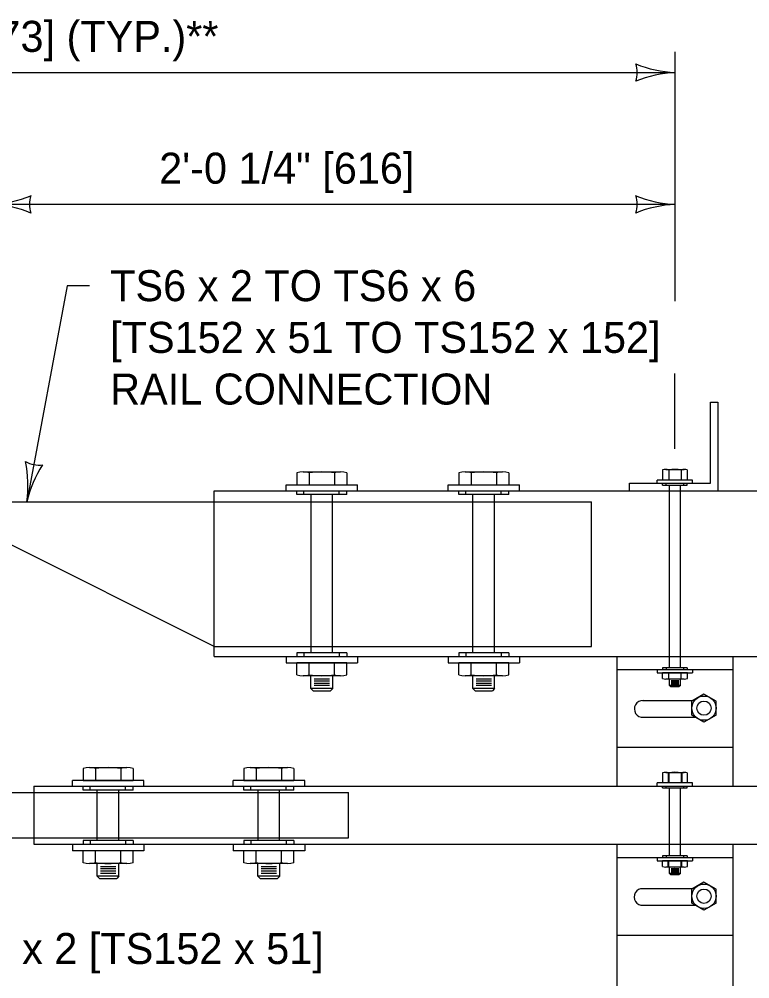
# Model space of a CAD drawing. Extents: x 49991.4 to 50021, y 49987.6 to 50011.4.
# Drawn here: x 50002.34 to 50003.755, y 49993.066 to 49994.923 of the extents above; entities that cross this region are included whole.
import ezdxf

# ---------------------------------------------------------------- set-up
doc = ezdxf.new("R2010")
doc.units = 0
for name, color, linetype in [('Level 1', 7, 'Continuous'), ('Level 2', 7, 'Continuous'), ('Level 3', 7, 'Continuous'), ('Level 4', 7, 'Continuous')]:
    doc.layers.add(name, color=color, linetype=linetype)

msp = doc.modelspace()

# ---------------------------------------------------------------- linework, layer by layer
at = {"layer": 'Level 1'}
for p, q in [((50003.6785, 49994.0248), (50003.6785, 49994.1815)), ((50003.6785, 49994.1815), (50003.6926, 49994.1815)), ((50003.6926, 49994.1815), (50003.6926, 49994.0102)), ((50002.8775, 49994.0452), (50002.8775, 49994.0221)), ((50002.8896, 49994.0467), (50002.9619, 49994.0467)), ((50002.9014, 49994.0452), (50002.9014, 49994.0222)), ((50002.9502, 49994.0452), (50002.9502, 49994.0222)), ((50002.9741, 49994.0452), (50002.9741, 49994.0221)), ((50003.1911, 49994.0452), (50003.1911, 49994.0221)), ((50003.2032, 49994.0467), (50003.2755, 49994.0467)), ((50003.215, 49994.0452), (50003.215, 49994.0222)), ((50003.2638, 49994.0452), (50003.2638, 49994.0222)), ((50003.2877, 49994.0452), (50003.2877, 49994.0221)), ((50003.5856, 49994.0508), (50003.5856, 49994.031)), ((50003.5916, 49994.0516), (50003.6275, 49994.0516)), ((50003.5975, 49994.0509), (50003.5975, 49994.031)), ((50003.6216, 49994.0509), (50003.6216, 49994.031)), ((50003.6335, 49994.0508), (50003.6335, 49994.031)), ((50003.5213, 49994.0107), (50003.5213, 49994.0248)), ((50003.5213, 49994.0248), (50003.6785, 49994.0248)), ((50003.6437, 49994.031), (50003.5754, 49994.031)), ((50003.5754, 49994.0248), (50003.5754, 49994.031)), ((50003.6437, 49994.0248), (50003.6437, 49994.031)), ((50002.717, 49993.6897), (50002.717, 49994.0102)), ((50002.717, 49994.0102), (50003.7869, 49994.0102)), ((50002.8568, 49994.0221), (50002.995, 49994.0221)), ((50002.8568, 49994.0102), (50002.8568, 49994.0221)), ((50002.8775, 49994.0221), (50002.9741, 49994.0221)), ((50002.995, 49994.0102), (50002.995, 49994.0221)), ((50003.1704, 49994.0221), (50003.3082, 49994.0221)), ((50003.1704, 49994.0102), (50003.1704, 49994.0221)), ((50003.1808, 49994.0221), (50003.2979, 49994.0221)), ((50003.1911, 49994.0221), (50003.2877, 49994.0221)), ((50003.3082, 49994.0102), (50003.3082, 49994.0221)), ((50002.2862, 49993.9889), (50002.717, 49993.9889)), ((50002.717, 49993.7093), (50002.2992, 49993.9177)), ((50002.717, 49993.6897), (50003.7104, 49993.6897)), ((50002.8568, 49993.6897), (50002.8568, 49993.6771)), ((50002.995, 49993.6897), (50002.995, 49993.6771)), ((50003.1704, 49993.6897), (50003.1704, 49993.6771)), ((50003.3082, 49993.6897), (50003.3082, 49993.6771)), ((50003.4976, 49993.4387), (50003.4976, 49993.6897)), ((50003.7104, 49993.6897), (50004.1738, 49993.6897)), ((50003.7222, 49993.4387), (50003.7222, 49993.6897)), ((50002.8568, 49993.6771), (50002.995, 49993.6771)), ((50002.9741, 49993.6771), (50002.8775, 49993.6771)), ((50002.8775, 49993.654), (50002.8775, 49993.6771)), ((50002.9014, 49993.654), (50002.9014, 49993.677)), ((50002.9502, 49993.654), (50002.9502, 49993.677)), ((50002.9741, 49993.654), (50002.9741, 49993.6771)), ((50003.1704, 49993.6771), (50003.3082, 49993.6771)), ((50003.1808, 49993.6771), (50003.2884, 49993.6771)), ((50003.2877, 49993.6771), (50003.1911, 49993.6771)), ((50003.1911, 49993.654), (50003.1911, 49993.6771)), ((50003.215, 49993.654), (50003.215, 49993.677)), ((50003.2638, 49993.654), (50003.2638, 49993.677)), ((50003.2877, 49993.654), (50003.2877, 49993.6771)), ((50002.962, 49993.6525), (50002.8897, 49993.6525)), ((50002.9046, 49993.6276), (50002.9046, 49993.6526)), ((50002.9468, 49993.6276), (50002.9468, 49993.6526)), ((50003.2756, 49993.6525), (50003.2033, 49993.6525)), ((50003.2182, 49993.6276), (50003.2182, 49993.6526)), ((50003.2604, 49993.6276), (50003.2604, 49993.6526)), ((50003.4976, 49993.6645), (50003.7222, 49993.6645)), ((50003.5754, 49993.6645), (50003.5754, 49993.6583)), ((50003.5754, 49993.6583), (50003.6437, 49993.6583)), ((50003.6336, 49993.6583), (50003.5857, 49993.6583)), ((50003.5857, 49993.6469), (50003.5857, 49993.6583)), ((50003.5975, 49993.6469), (50003.5975, 49993.6583)), ((50003.6217, 49993.6469), (50003.6217, 49993.6583)), ((50003.6336, 49993.6469), (50003.6336, 49993.6583)), ((50003.6437, 49993.6645), (50003.6437, 49993.6583)), ((50002.9107, 49993.6467), (50002.9404, 49993.6467)), ((50002.9107, 49993.6425), (50002.9404, 49993.6425)), ((50002.9107, 49993.6382), (50002.9404, 49993.6382)), ((50002.9107, 49993.634), (50002.9404, 49993.634)), ((50003.2243, 49993.6467), (50003.254, 49993.6467)), ((50003.2243, 49993.6425), (50003.254, 49993.6425)), ((50003.2243, 49993.6382), (50003.254, 49993.6382)), ((50003.2243, 49993.634), (50003.254, 49993.634)), ((50003.6275, 49993.6461), (50003.5917, 49993.6461)), ((50003.5991, 49993.6338), (50003.6012, 49993.6317)), ((50003.5992, 49993.6338), (50003.5992, 49993.6461)), ((50003.62, 49993.6338), (50003.5992, 49993.6338)), ((50003.6022, 49993.6433), (50003.6169, 49993.6433)), ((50003.6022, 49993.6412), (50003.6169, 49993.6412)), ((50003.6022, 49993.6391), (50003.6169, 49993.6391)), ((50003.6022, 49993.637), (50003.6169, 49993.637)), ((50003.62, 49993.6338), (50003.6179, 49993.6317)), ((50003.62, 49993.6338), (50003.62, 49993.6461)), ((50002.9468, 49993.6276), (50002.9046, 49993.6276)), ((50002.9046, 49993.6276), (50002.9088, 49993.6234)), ((50002.9088, 49993.6234), (50002.9426, 49993.6234)), ((50002.9468, 49993.6276), (50002.9426, 49993.6234)), ((50003.2604, 49993.6276), (50003.2182, 49993.6276)), ((50003.2182, 49993.6276), (50003.2224, 49993.6234)), ((50003.2224, 49993.6234), (50003.2562, 49993.6234)), ((50003.2604, 49993.6276), (50003.2562, 49993.6234)), ((50003.6012, 49993.6317), (50003.6179, 49993.6317)), ((50003.6658, 49993.6169), (50003.6422, 49993.6033)), ((50003.6893, 49993.6033), (50003.6658, 49993.6169)), ((50003.5465, 49993.6043), (50003.644, 49993.6043)), ((50003.6422, 49993.5761), (50003.6422, 49993.6033)), ((50003.6893, 49993.5761), (50003.6893, 49993.6033)), ((50003.5481, 49993.5722), (50003.6491, 49993.5722)), ((50003.6658, 49993.5625), (50003.6422, 49993.5761)), ((50003.6893, 49993.5761), (50003.6658, 49993.5625)), ((50003.4976, 49993.5141), (50003.7222, 49993.5141)), ((50002.4636, 49993.4731), (50002.4636, 49993.45)), ((50002.4757, 49993.4746), (50002.548, 49993.4746)), ((50002.4875, 49993.4731), (50002.4875, 49993.4501)), ((50002.5363, 49993.4731), (50002.5363, 49993.4501)), ((50002.5602, 49993.4731), (50002.5602, 49993.45)), ((50002.7749, 49993.4731), (50002.7749, 49993.45)), ((50002.787, 49993.4746), (50002.8593, 49993.4746)), ((50002.7988, 49993.4731), (50002.7988, 49993.4501)), ((50002.8476, 49993.4731), (50002.8476, 49993.4501)), ((50002.8715, 49993.4731), (50002.8715, 49993.45)), ((50003.5916, 49993.4655), (50003.6275, 49993.4655)), ((50002.5812, 49993.45), (50002.4429, 49993.45)), ((50002.4429, 49993.4387), (50002.4429, 49993.45)), ((50002.4636, 49993.45), (50002.5602, 49993.45)), ((50002.5812, 49993.4387), (50002.5812, 49993.45)), ((50002.8925, 49993.45), (50002.7542, 49993.45)), ((50002.7542, 49993.4387), (50002.7542, 49993.45)), ((50002.7749, 49993.45), (50002.8715, 49993.45)), ((50002.8925, 49993.4387), (50002.8925, 49993.45)), ((50003.5856, 49993.4647), (50003.5856, 49993.4449)), ((50003.5975, 49993.4648), (50003.5975, 49993.4449)), ((50003.6216, 49993.4648), (50003.6216, 49993.4449)), ((50003.6335, 49993.4647), (50003.6335, 49993.4449)), ((50002.3682, 49993.4387), (50003.4526, 49993.4387)), ((50002.3682, 49993.4387), (50002.3682, 49993.3264)), ((50003.4526, 49993.4387), (50004.1738, 49993.4387)), ((50003.6437, 49993.4449), (50003.5754, 49993.4449)), ((50003.5754, 49993.4387), (50003.5754, 49993.4449)), ((50003.6437, 49993.4387), (50003.6437, 49993.4449)), ((50002.2862, 49993.4266), (50002.3682, 49993.4266)), ((50002.2862, 49993.3388), (50002.3682, 49993.3388)), ((50002.3682, 49993.3264), (50003.4526, 49993.3264)), ((50002.4429, 49993.3264), (50002.4429, 49993.3138)), ((50002.5812, 49993.3264), (50002.5812, 49993.3138)), ((50002.7542, 49993.3264), (50002.7542, 49993.3138)), ((50002.8925, 49993.3264), (50002.8925, 49993.3138)), ((50003.4526, 49993.3264), (50004.1738, 49993.3264)), ((50003.4976, 49992.5551), (50003.4976, 49993.3264)), ((50003.7222, 49992.5551), (50003.7222, 49993.3264)), ((50002.5812, 49993.3138), (50002.4429, 49993.3138)), ((50002.5602, 49993.3138), (50002.4636, 49993.3138)), ((50002.4636, 49993.2907), (50002.4636, 49993.3138)), ((50002.4875, 49993.2907), (50002.4875, 49993.3137)), ((50002.5363, 49993.2907), (50002.5363, 49993.3137)), ((50002.5602, 49993.2907), (50002.5602, 49993.3138)), ((50002.8925, 49993.3138), (50002.7542, 49993.3138)), ((50002.8715, 49993.3138), (50002.7749, 49993.3138)), ((50002.7749, 49993.2907), (50002.7749, 49993.3138)), ((50002.7988, 49993.2907), (50002.7988, 49993.3137)), ((50002.8476, 49993.2907), (50002.8476, 49993.3137)), ((50002.8715, 49993.2907), (50002.8715, 49993.3138)), ((50003.4976, 49993.3006), (50003.7222, 49993.3006)), ((50003.5754, 49993.3006), (50003.5754, 49993.2944)), ((50003.6437, 49993.3006), (50003.6437, 49993.2944)), ((50002.5481, 49993.2892), (50002.4758, 49993.2892)), ((50002.4907, 49993.2643), (50002.4907, 49993.2893)), ((50002.4968, 49993.2834), (50002.5265, 49993.2834)), ((50002.5329, 49993.2643), (50002.5329, 49993.2893)), ((50002.8594, 49993.2892), (50002.7871, 49993.2892)), ((50002.802, 49993.2643), (50002.802, 49993.2893)), ((50002.8081, 49993.2834), (50002.8378, 49993.2834)), ((50002.8442, 49993.2643), (50002.8442, 49993.2893)), ((50003.5754, 49993.2944), (50003.6437, 49993.2944)), ((50003.6336, 49993.2944), (50003.5857, 49993.2944)), ((50003.5857, 49993.283), (50003.5857, 49993.2944)), ((50003.6275, 49993.2822), (50003.5917, 49993.2822)), ((50003.5975, 49993.283), (50003.5975, 49993.2944)), ((50003.5992, 49993.2699), (50003.5992, 49993.2822)), ((50003.62, 49993.2699), (50003.62, 49993.2822)), ((50003.6217, 49993.283), (50003.6217, 49993.2944)), ((50003.6336, 49993.283), (50003.6336, 49993.2944)), ((50002.5329, 49993.2643), (50002.4907, 49993.2643)), ((50002.4907, 49993.2643), (50002.4949, 49993.2601)), ((50002.4968, 49993.2792), (50002.5265, 49993.2792)), ((50002.4968, 49993.2749), (50002.5265, 49993.2749)), ((50002.4968, 49993.2707), (50002.5265, 49993.2707)), ((50002.5329, 49993.2643), (50002.5287, 49993.2601)), ((50002.8442, 49993.2643), (50002.802, 49993.2643)), ((50002.802, 49993.2643), (50002.8062, 49993.2601)), ((50002.8081, 49993.2792), (50002.8378, 49993.2792)), ((50002.8081, 49993.2749), (50002.8378, 49993.2749)), ((50002.8081, 49993.2707), (50002.8378, 49993.2707)), ((50002.8442, 49993.2643), (50002.84, 49993.2601)), ((50003.5991, 49993.2699), (50003.6012, 49993.2678)), ((50003.62, 49993.2699), (50003.5992, 49993.2699)), ((50003.6012, 49993.2678), (50003.6179, 49993.2678)), ((50003.6022, 49993.2794), (50003.6169, 49993.2794)), ((50003.6022, 49993.2773), (50003.6169, 49993.2773)), ((50003.6022, 49993.2752), (50003.6169, 49993.2752)), ((50003.6022, 49993.2731), (50003.6169, 49993.2731)), ((50003.62, 49993.2699), (50003.6179, 49993.2678)), ((50002.4949, 49993.2601), (50002.5287, 49993.2601)), ((50002.8062, 49993.2601), (50002.84, 49993.2601)), ((50003.6658, 49993.253), (50003.6422, 49993.2394)), ((50003.6893, 49993.2394), (50003.6658, 49993.253)), ((50003.5465, 49993.2404), (50003.644, 49993.2404)), ((50003.6422, 49993.2122), (50003.6422, 49993.2394)), ((50003.6893, 49993.2122), (50003.6893, 49993.2394)), ((50003.5481, 49993.2083), (50003.6491, 49993.2083)), ((50003.6658, 49993.1986), (50003.6422, 49993.2122)), ((50003.6893, 49993.2122), (50003.6658, 49993.1986)), ((50003.4976, 49993.1502), (50003.7222, 49993.1502))]:
    msp.add_line(p, q, dxfattribs=at)
for centre in [(50003.6658, 49993.5897), (50003.6658, 49993.2258)]:
    msp.add_circle(centre, 0.0235, dxfattribs=at)
for centre, start, end in [((50003.547, 49993.5882), 87.1656, 275.1264), ((50003.5467, 49993.2243), 86.9502, 274.911)]:
    msp.add_arc(centre, 0.0161, start, end, dxfattribs=at)
for centre, major_axis, start_param, end_param in [((50002.8896, 49994.035), (0.0242, 0), 1.056847, 2.094396), ((50002.9258, 49994), (0.0966, 0), 1.315951, 1.825641), ((50002.962, 49994.035), (0.0242, 0), 1.047198, 2.084746), ((50003.2032, 49994.035), (0.0242, 0), 1.056847, 2.094396), ((50003.2394, 49994), (0.0966, 0), 1.315951, 1.825641), ((50003.2756, 49994.035), (0.0242, 0), 1.047198, 2.084746), ((50003.5916, 49994.0458), (0.012, 0), 1.056847, 2.094396), ((50003.6096, 49994.0285), (0.0479, 0), 1.315951, 1.825641), ((50003.6275, 49994.0458), (0.012, 0), 1.047198, 2.084746), ((50002.8896, 49993.6642), (-0.0242, 0), 1.047198, 2.084746), ((50002.9258, 49993.6992), (-0.0966, 0), 1.315951, 1.825641), ((50002.962, 49993.6642), (-0.0242, 0), 1.056847, 2.094396), ((50003.2032, 49993.6642), (-0.0242, 0), 1.047198, 2.084746), ((50003.2394, 49993.6992), (-0.0966, 0), 1.315951, 1.825641), ((50003.2756, 49993.6642), (-0.0242, 0), 1.056847, 2.094396), ((50003.5917, 49993.6519), (-0.012, 0), 1.047198, 2.084746), ((50003.6096, 49993.6693), (-0.0479, 0), 1.315951, 1.825641), ((50003.6276, 49993.6519), (-0.012, 0), 1.056847, 2.094396), ((50002.4757, 49993.4629), (0.0242, 0), 1.056847, 2.094396), ((50002.5119, 49993.4279), (0.0966, 0), 1.315951, 1.825641), ((50002.5481, 49993.4629), (0.0242, 0), 1.047198, 2.084746), ((50002.787, 49993.4629), (0.0242, 0), 1.056847, 2.094396), ((50002.8232, 49993.4279), (0.0966, 0), 1.315951, 1.825641), ((50002.8594, 49993.4629), (0.0242, 0), 1.047198, 2.084746), ((50003.5916, 49993.4597), (0.012, 0), 1.056847, 2.094396), ((50003.6096, 49993.4424), (0.0479, 0), 1.315951, 1.825641), ((50003.6275, 49993.4597), (0.012, 0), 1.047198, 2.084746), ((50002.4757, 49993.3009), (-0.0242, 0), 1.047198, 2.084746), ((50002.5119, 49993.3359), (-0.0966, 0), 1.315951, 1.825641), ((50002.5481, 49993.3009), (-0.0242, 0), 1.056847, 2.094396), ((50002.787, 49993.3009), (-0.0242, 0), 1.047198, 2.084746), ((50002.8232, 49993.3359), (-0.0966, 0), 1.315951, 1.825641), ((50002.8594, 49993.3009), (-0.0242, 0), 1.056847, 2.094396), ((50003.5917, 49993.288), (-0.012, 0), 1.047198, 2.084746), ((50003.6096, 49993.3054), (-0.0479, 0), 1.315951, 1.825641), ((50003.6276, 49993.288), (-0.012, 0), 1.056847, 2.094396)]:
    msp.add_ellipse(centre, major_axis=major_axis, ratio=0.483301, start_param=start_param, end_param=end_param, dxfattribs=at)
at = {"layer": 'Level 3'}
for p, q in [((50003.6098, 49994.3772), (50003.6098, 49994.8597)), ((50001.2319, 49994.8197), (50003.6098, 49994.8197)), ((50003.6098, 49994.5646), (50002.2862, 49994.5646)), ((50002.4325, 49994.4072), (50002.3544, 49993.9889)), ((50002.4758, 49994.4072), (50002.4325, 49994.4072)), ((50003.6096, 49994.0916), (50003.6096, 49994.2372))]:
    msp.add_line(p, q, dxfattribs=at)
for centre, radius, start, end in [((50003.619, 49995.0418), 0.2223, 247.456, 267.6395), ((50003.4816, 49994.8197), 0.0548, 342.1388, 17.8612), ((50003.6213, 49994.587), 0.233, 92.8273, 112.0772), ((50002.2747, 49994.7973), 0.233, 272.8273, 292.0772), ((50002.4144, 49994.5646), 0.0548, 162.1388, 197.8612), ((50003.619, 49994.7867), 0.2223, 247.456, 267.6395), ((50003.4816, 49994.5646), 0.0548, 342.1388, 17.8612), ((50002.277, 49994.3425), 0.2223, 67.456, 87.6395), ((50003.6213, 49994.3319), 0.233, 92.8273, 112.0772), ((50002.378, 49994.1149), 0.0548, 241.5671, 277.2895), ((50002.1236, 49994.0203), 0.233, 352.2556, 11.5055), ((50002.5711, 49993.9391), 0.2223, 146.8843, 167.0678)]:
    msp.add_arc(centre, radius, start, end, dxfattribs=at)
at = {"layer": 'Level 4'}
for p, q in [((50003.5856, 49994.0213), (50003.5856, 49994.0248)), ((50003.5928, 49994.0213), (50003.5928, 49994.0248)), ((50003.6267, 49994.0213), (50003.6267, 49994.0248)), ((50003.6334, 49994.0213), (50003.6334, 49994.0248)), ((50002.8775, 49994.0029), (50002.8775, 49994.0108)), ((50002.8911, 49994.0029), (50002.8911, 49994.0108)), ((50002.9595, 49994.0029), (50002.9595, 49994.0108)), ((50002.9741, 49994.0029), (50002.9741, 49994.0108)), ((50003.1911, 49994.0029), (50003.1911, 49994.0108)), ((50003.2047, 49994.0029), (50003.2047, 49994.0108)), ((50003.2731, 49994.0029), (50003.2731, 49994.0108)), ((50003.2877, 49994.0029), (50003.2877, 49994.0108)), ((50003.5856, 49994.0213), (50003.6334, 49994.0213)), ((50003.5991, 49993.668), (50003.5991, 49994.0213)), ((50003.62, 49993.668), (50003.62, 49994.0213)), ((50002.717, 49993.9889), (50003.4482, 49993.9889)), ((50002.9741, 49994.0029), (50002.8775, 49994.0029)), ((50002.9048, 49993.6969), (50002.9048, 49994.0029)), ((50002.9462, 49993.6969), (50002.9462, 49994.0029)), ((50003.2877, 49994.0029), (50003.1911, 49994.0029)), ((50003.2184, 49993.6969), (50003.2184, 49994.0029)), ((50003.2598, 49993.6969), (50003.2598, 49994.0029)), ((50003.4482, 49993.7093), (50003.4482, 49993.9889)), ((50002.717, 49993.7093), (50003.4482, 49993.7093)), ((50002.9741, 49993.6969), (50002.8775, 49993.6969)), ((50002.8775, 49993.6969), (50002.8775, 49993.6897)), ((50002.8911, 49993.6969), (50002.8911, 49993.6897)), ((50002.9595, 49993.6969), (50002.9595, 49993.6897)), ((50002.9741, 49993.6969), (50002.9741, 49993.6897)), ((50003.2877, 49993.6969), (50003.1911, 49993.6969)), ((50003.1911, 49993.6969), (50003.1911, 49993.6897)), ((50003.2047, 49993.6969), (50003.2047, 49993.6897)), ((50003.2731, 49993.6969), (50003.2731, 49993.6897)), ((50003.2877, 49993.6969), (50003.2877, 49993.6897)), ((50003.5857, 49993.668), (50003.5857, 49993.6645)), ((50003.6335, 49993.668), (50003.5857, 49993.668)), ((50003.5924, 49993.668), (50003.5924, 49993.6645)), ((50003.6263, 49993.668), (50003.6263, 49993.6645)), ((50003.6335, 49993.668), (50003.6335, 49993.6645)), ((50003.5962, 49993.4651), (50003.5962, 49993.4449)), ((50003.623, 49993.4651), (50003.623, 49993.4449)), ((50002.4636, 49993.4308), (50002.4636, 49993.4387)), ((50002.5602, 49993.4308), (50002.4636, 49993.4308)), ((50002.4772, 49993.4308), (50002.4772, 49993.4387)), ((50002.4909, 49993.3336), (50002.4909, 49993.4308)), ((50002.5323, 49993.3336), (50002.5323, 49993.4308)), ((50002.5456, 49993.4308), (50002.5456, 49993.4387)), ((50002.5602, 49993.4308), (50002.5602, 49993.4387)), ((50002.7749, 49993.4308), (50002.7749, 49993.4387)), ((50002.8715, 49993.4308), (50002.7749, 49993.4308)), ((50002.7885, 49993.4308), (50002.7885, 49993.4387)), ((50002.8022, 49993.3336), (50002.8022, 49993.4308)), ((50002.8436, 49993.3336), (50002.8436, 49993.4308)), ((50002.8569, 49993.4308), (50002.8569, 49993.4387)), ((50002.8715, 49993.4308), (50002.8715, 49993.4387)), ((50003.5856, 49993.4352), (50003.5856, 49993.4387)), ((50003.5856, 49993.4352), (50003.6334, 49993.4352)), ((50003.5928, 49993.4352), (50003.5928, 49993.4387)), ((50003.5991, 49993.3041), (50003.5991, 49993.4352)), ((50003.62, 49993.3041), (50003.62, 49993.4352)), ((50003.6267, 49993.4352), (50003.6267, 49993.4387)), ((50003.6334, 49993.4352), (50003.6334, 49993.4387)), ((50002.3682, 49993.4266), (50002.9771, 49993.4266)), ((50002.9771, 49993.3388), (50002.9771, 49993.4266)), ((50002.3682, 49993.3388), (50002.9771, 49993.3388)), ((50002.5602, 49993.3336), (50002.4636, 49993.3336)), ((50002.4636, 49993.3336), (50002.4636, 49993.3264)), ((50002.4772, 49993.3336), (50002.4772, 49993.3264)), ((50002.5456, 49993.3336), (50002.5456, 49993.3264)), ((50002.5602, 49993.3336), (50002.5602, 49993.3264)), ((50002.8715, 49993.3336), (50002.7749, 49993.3336)), ((50002.7749, 49993.3336), (50002.7749, 49993.3264)), ((50002.7885, 49993.3336), (50002.7885, 49993.3264)), ((50002.8569, 49993.3336), (50002.8569, 49993.3264)), ((50002.8715, 49993.3336), (50002.8715, 49993.3264)), ((50003.5857, 49993.3041), (50003.5857, 49993.3006)), ((50003.6335, 49993.3041), (50003.5857, 49993.3041)), ((50003.5924, 49993.3041), (50003.5924, 49993.3006)), ((50003.6263, 49993.3041), (50003.6263, 49993.3006)), ((50003.6335, 49993.3041), (50003.6335, 49993.3006)), ((50003.5962, 49993.2826), (50003.5962, 49993.2944)), ((50003.623, 49993.2826), (50003.623, 49993.2944))]:
    msp.add_line(p, q, dxfattribs=at)
for centre in [(50003.6658, 49993.5897), (50003.6658, 49993.2258)]:
    msp.add_circle(centre, 0.0138, dxfattribs=at)

# ---------------------------------------------------------------- texts
at = {"layer": 'Level 2'}
for s, p in [('3\'-6 1/4" [1073] (TYP.)**', (50001.8701, 49994.8597)), ('2\'-0 1/4" [616]', (50002.6107, 49994.6046)), ('TS6 x 2 TO TS6 x 6 ', (50002.5158, 49994.3772)), ('[TS152 x 51 TO TS152 x 152]', (50002.5158, 49994.2772)), ('RAIL CONNECTION', (50002.5158, 49994.1772)), ('TS6 x 2 [TS152 x 51] ', (50002.1758, 49993.0946))]:
    msp.add_text(s, height=0.06, dxfattribs=at).set_placement(p)

doc.saveas('drawing.dxf')
